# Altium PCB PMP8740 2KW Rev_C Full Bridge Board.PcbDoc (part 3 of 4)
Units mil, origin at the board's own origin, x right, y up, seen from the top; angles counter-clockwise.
Board outline 10366.14 x 5900 mil, 2 copper layers (Top Layer, Bottom Layer), stack 62 mil thick; 355 components, 213 nets, 1059 pads, 574 vias.
Unrouted connection lines stored in the file: 2.
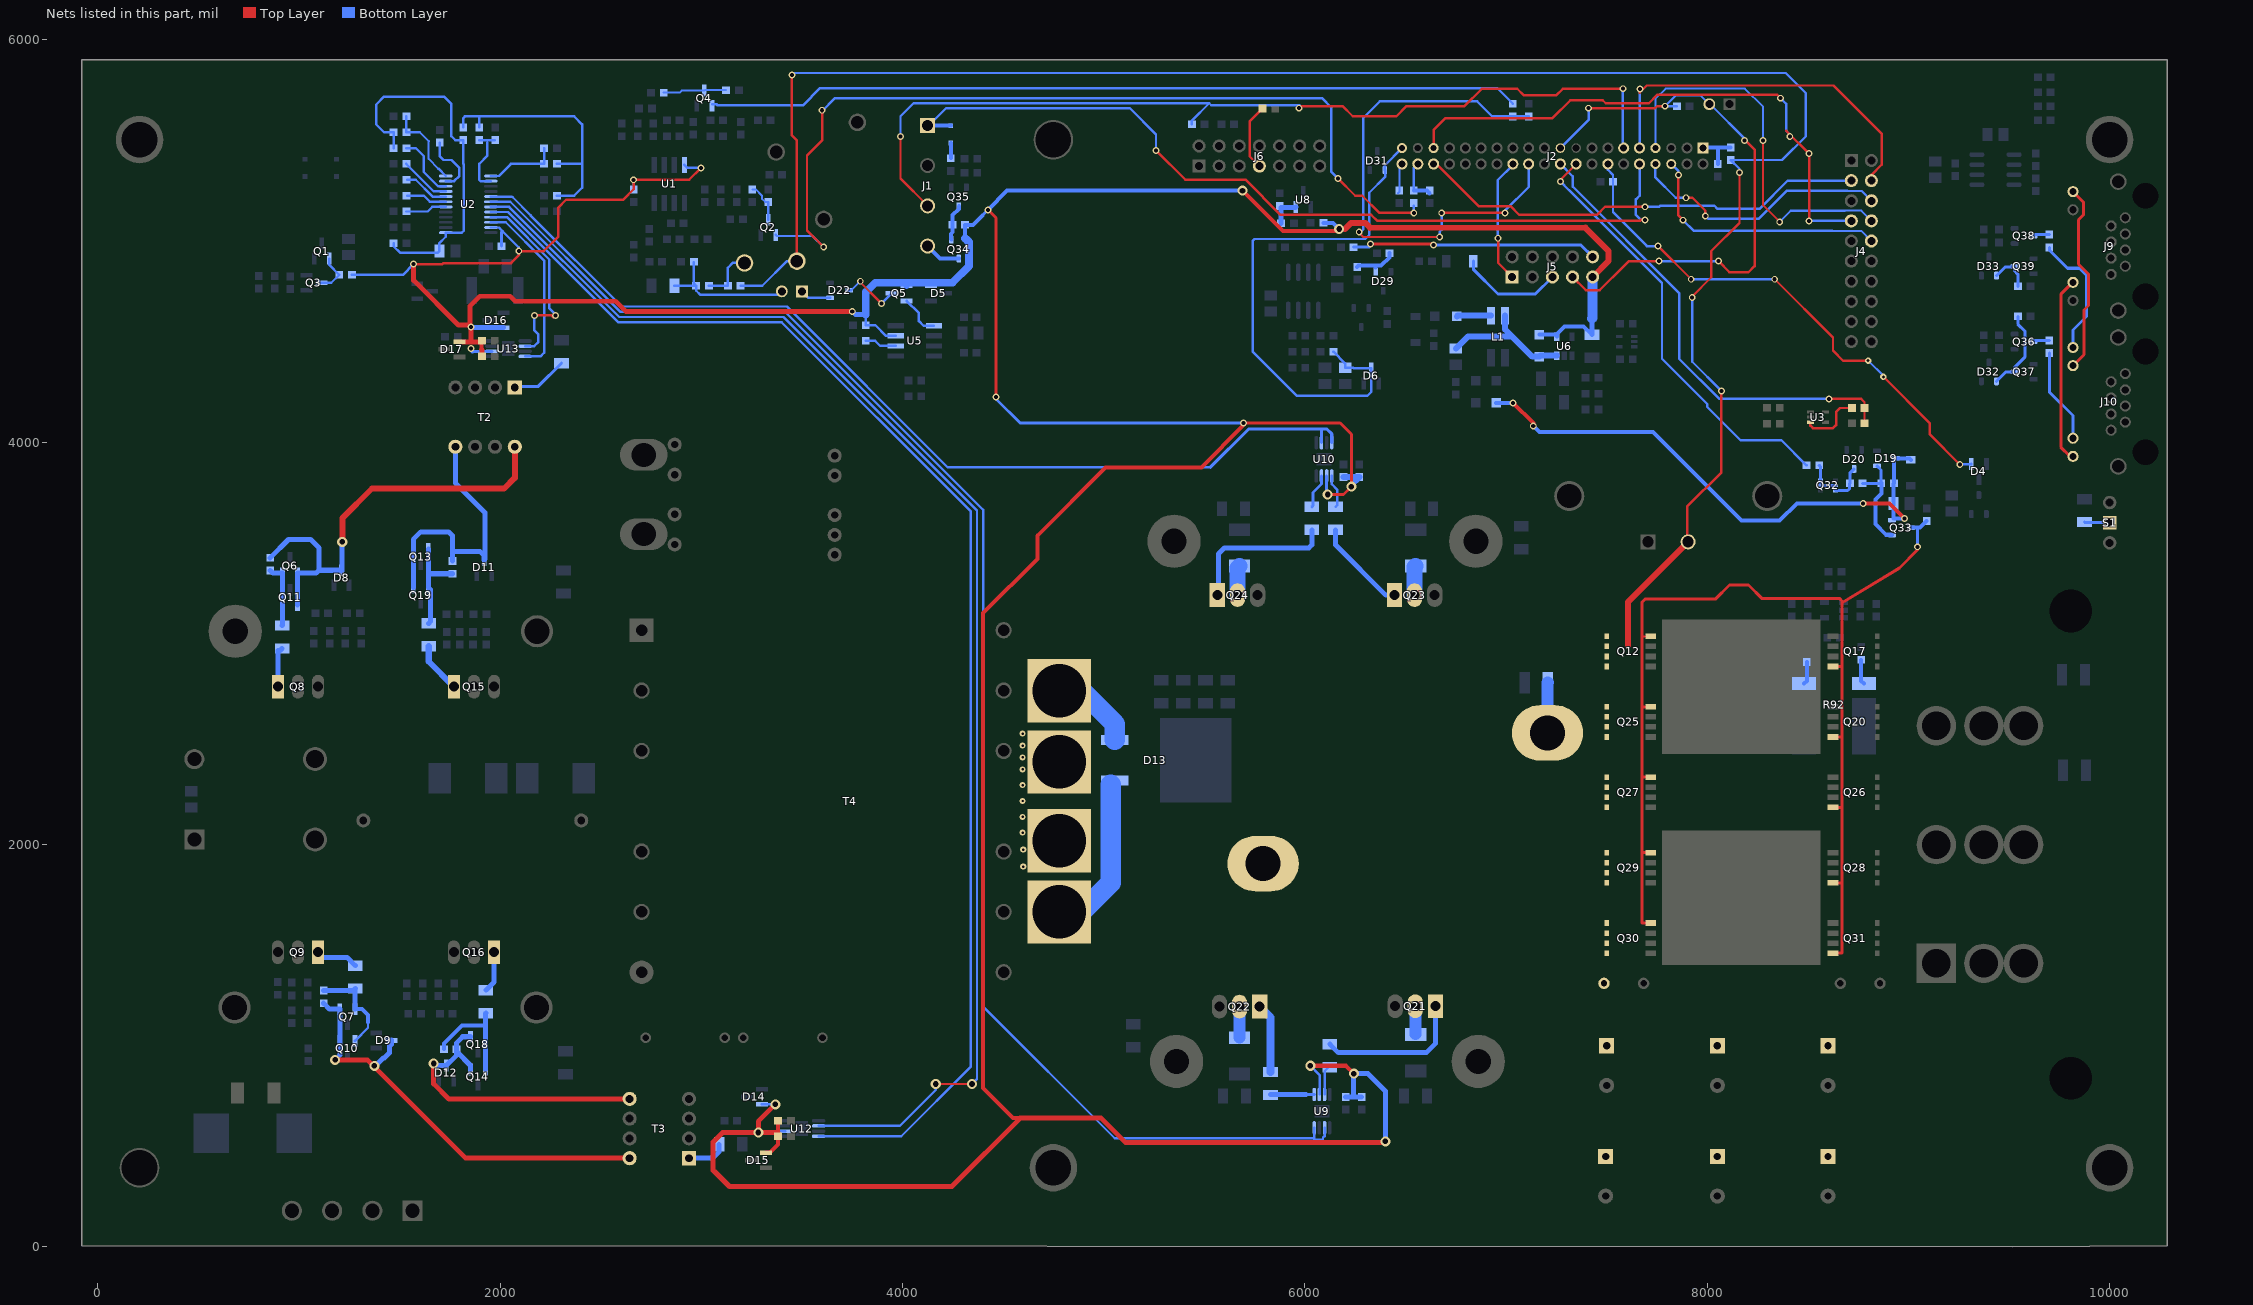
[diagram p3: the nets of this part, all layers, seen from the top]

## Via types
v1: diameter 34, hole 20, Top Layer to Bottom Layer, 367 vias
v2: diameter 50, hole 28, Top Layer to Bottom Layer, 60 vias
v3: diameter 34, hole 20, Top Layer to Bottom Layer, tented both sides, 45 vias
v4: diameter 30, hole 12, Top Layer to Bottom Layer, tented both sides, 34 vias
v5: diameter 50, hole 28, Top Layer to Bottom Layer, tented both sides, 33 vias
v6: diameter 19.68, hole 7.87, Top Layer to Bottom Layer, tented both sides, 20 vias
v7: diameter 34, hole 22, Top Layer to Bottom Layer, 11 vias
v8: diameter 34, hole 15, Top Layer to Bottom Layer, 3 vias
v9: diameter 30, hole 20, Top Layer to Bottom Layer, tented both sides, 1 vias

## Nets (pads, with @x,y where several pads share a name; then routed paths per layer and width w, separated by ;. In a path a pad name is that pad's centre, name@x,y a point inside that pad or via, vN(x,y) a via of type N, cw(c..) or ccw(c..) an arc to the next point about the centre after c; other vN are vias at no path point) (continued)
NetD8_3: D8.3 Q6.1 Q11.1 R72.1 T2.8 | length 2152.7
  Top Layer w30: v5(1215,3505) 1215.91,3505.91 1215.91,3622.88 1363.02,3770 2020,3770 2072.64,3822.64 T2.8@2072.64,3977.36
  Bottom Layer w25: R72.1@857.05,3425.55 947.6,3516.1 1057.83,3516.1 1099.17,3474.76 1099.17,3363.54 ; Q11.1@992.87,3191.3 Q6.1@992.87,3348.78 1084.41,3348.78 1099.17,3363.54 ; v5(1215,3505) 1215,3359.92 D8.3@1211.38,3363.54 1099.17,3363.54
NetD9_3: D9.3 Q7.1 Q10.1 R75.1 T3.8 | length 2210.7
  Top Layer w25: v5(1180,930) 1340,930 1829.02,440.98 T3.8@2643.62,440.98
  Bottom Layer w25: R75.1@1122.52,1211.3 1152.05,1181.77 Q7.1@1203.23,1181.77 Q10.1@1203.23,1024.29 1203.23,953.23 v5(1180,930) ; v5(1375,900) 1375,895 1420,940 1425,940 1449.29,964.29 1449.29,997.72 1459.13,1007.56 1459.13,1028.46 D9.3@1445.16,1028.46
NetD11_3: D11.3 Q13.1 Q19.1 R85.1 T2.5 | length 1391.2
  Bottom Layer w25: Q19.1@1568.23,3277.17 Q13.1@1568.23,3469.09 1568.23,3517.32 1605.63,3554.72 1743.43,3554.72 1763.11,3535.04 1763.11,3456.3 ; R85.1@1763.11,3409.06 1763.11,3456.3 ; T2.5@1777.36,3977.36 1777.36,3797.64 1925,3650 1925,3419.37 D11.3@1920.59,3414.96 1920.59,3436.61 1905.28,3451.93 ; 1900.91,3456.3 1763.11,3456.3
NetD12_3: D12.3 Q14.1 Q18.1 R88.1 T3.5 | length 1506.6
  Top Layer w25: v5(1669.33,911.97) 1669.33,810.67 1745,735 2642.36,735 T3.5@2643.62,736.26
  Bottom Layer w25: v5(1669.33,911.97) 1679.17,902.13 D12.3@1732.32,902.13 1783.5,953.31 R88.1@1783.5,971.02 ; Q14.1@1852.4,882.44 1852.4,902.13 R88.1@1783.5,971.02 ; Q18.1@1852.4,1044.84 1814.02,1044.84 1783.5,1014.33 R88.1@1783.5,982.83 R88.1@1783.5,971.02
NetD13_1: D13.1 Q21.2 Q22.2 R125.2 R126.2 T4.13 | length 1109.7
  Bottom Layer w59.06: R125.2@5675,1040.55 Q22.2@5675,1194.68 ; R126.2@6548.76,1057.2 Q21.2@6548.76,1196.57
  Bottom Layer w100: T4.13@4770,1660 4885,1660 5035,1810 D13.1@5035,2299.06
NetD13_3: D13.3 Q23.2 Q24.2 R127.2 R128.2 T4.16 | length 721.2
  Bottom Layer w80: Q24.2@5665,3240 5665,3374.45 R128.2@5675,3384.45 ; Q23.2@6545,3240 6545,3379.45 R127.2@6550,3384.45
  Bottom Layer w100: T4.16@4778.23,2765 4890,2765 5054.94,2600.06 D13.3@5054.94,2519
NetD19_1: D19.1 Q33.1 R80.1 R83.2 | length 509.1
  Bottom Layer w15: R83.2@8771.5,3795 8863.79,3795 8863.79,3861.57 D19.1@8842.76,3882.6
  Bottom Layer w20: R80.1@8864.89,3796.1 8864.89,3744.89 8835,3715 8835,3594.21 8889.21,3540 8915.35,3540 Q33.1@8917.76,3537.6
NetD20_3: D20.3 Q32.3 R83.1 | length 182
  Bottom Layer w15: Q32.3@8637.4,3759.41 8697.68,3759.41 8706,3767.73 8706,3792.5 R83.1@8708.5,3795 8708.5,3846.26 D20.3@8730,3867.76
NetD22_1: D22.1 J3.1 | length 153.2
  Bottom Layer w12: J3.1@3500,4750 3532.4,4717.6 D22.1@3639.8,4717.6
NetD22_3: D22.3 Q5.3 | length 311
  Top Layer w12: v1(3790,4800) 3785,4800 v1(3895,4690)
  Bottom Layer w12: D22.3@3734.29,4755 3745,4755 v1(3790,4800) ; v1@3895,4685 v1@3895,4689.49 ; v1(3895,4690) v1@3895,4689.49 ; Q5.3@3945.28,4739.77 v1@3895,4689.49
NetD24_1: D24.1 L1.4 | length 171.2
  Bottom Layer w30: D24.1@6755.12,4625 6759.45,4629.33 L1.4@6924.57,4629.33
NetD27_2: D27.2 L1.1 R91.2 U6.3 | length 689
  Bottom Layer w30: R91.2@6750,4465 6810,4525 7030,4525 ; L1.1@6995,4628.9 6995,4560 7030,4525 ; U6.3@7252.01,4430.31 7170.43,4430.31 D27.2@7165,4424.88 7130.12,4424.88 7030,4525
NetD28_1: D28.1 R105.2 | length 75.2
  Bottom Layer w20: R105.2@4240,5411.5 D28.1@4240,5486.69
NetD29_1: D29.1 R65.2 R67.1 | length 215
  Bottom Layer w20: R67.1@6260,4871.5 6265.75,4877.24 6342.64,4877.24 ; 6351.95,4867.93 6342.64,4877.24 ; R65.2@6421.5,4940 6420.99,4939.5 6420.99,4919 6379.23,4877.24 6342.64,4877.24
NetD32_1: D32.1 Q37.3 R118.2 | length 421.7
  Bottom Layer w15: D32.1@9437.4,4302.76 9437.76,4302.76 9485,4350 Q37.3@9527.76,4350 9527.76,4372.76 9580,4425 9580,4550 9543.5,4586.5 R118.2@9543.5,4625
NetD33_1: D33.1 Q39.3 R121.2 | length 216.4
  Bottom Layer w15: D33.1@9437.4,4827.76 9479.65,4870 9522.76,4870 Q39.3@9527.76,4875 9527.76,4850.67 9543.5,4834.92 R121.2@9543.5,4775
NetJ1_4: J1.4 Q34.3 | length 180.8
  Bottom Layer w20: J1.4@4125,4975 4187.24,4912.76 Q34.3@4280,4912.76
NetJ2_40: J2.40 R35.1 | length 153.8
  Bottom Layer w12: R35.1@6462.64,5237.4 6470,5244.76 6470,5370.75 J2.40@6482.32,5383.07
NetJ6_7: J6.7 R106.2 | length 333.1
  Top Layer w12: J6.7@5773.66,5372.44 5725,5421.1 5725,5594.25 R106.2@5789.41,5658.66
NetJ9_9: J9.9 J10.10 | length 949.1
  Top Layer w15: J10.10@9817.72,4380.31 9872.4,4435 9872.4,4657.4 9895,4680 9895,4835 9845,4885 9845,5105 9869.09,5129.09 9869.09,5194.09 J9.9@9817.72,5245.47
NetJ9_11: J9.11 J10.12 | length 924
  Top Layer w15: J10.12@9817.72,3929.53 9802.95,3929.53 9757.48,3975 9757.48,4735 9817.17,4794.69 J9.11@9817.72,4794.69
NetJ10_9: J10.9 R120.2 | length 637.7
  Bottom Layer w15: R120.2@9700,4968.5 9700,4955 9790.37,4864.63 9850.37,4864.63 9885,4830 9885,4625 9817.72,4557.72 J10.9@9817.72,4470.47
NetJ10_11: J10.11 R117.2 | length 472.6
  Bottom Layer w15: R117.2@9700,4443.5 9700,4250 9817.72,4132.28 J10.11@9817.72,4019.69
NetL3_1: L3.1 T4.14 T4.15
  other v4: 4600,1890 4600,1975 4597.28,2059.09 4597.28,2137.83 4597.28,2216.57 4597.28,2295.32 4597.28,2374.06 4597.28,2433.11 4597.28,2492.17 4597.28,2551.22
NetQ1_1: Q1.1 Q3.3 R30.2 | length 206
  Bottom Layer w12: Q3.3@1111.57,4792.52 1160.78,4792.52 R30.2@1200.15,4831.89 1150.94,4881.1 Q1.1@1150.94,4912.6
NetQ2_1: Q2.1 R28.2 | length 4435.6
  Top Layer w12: v1(3600,5650) 3600,5500 3525,5425 3525,5052.99 v3(3608.31,4969.69) ; v1(6165,5310) 6250,5225 6285,5225 6370,5140 v3(6541.38,5140)
  Bottom Layer w12: Q2.1@3370.12,5030.71 3375.83,5025 3552.99,5025 v3(3608.31,4969.69) ; v1@3600,5645 3665,5710 6085,5710 6130,5665 6130,5345 v1(6165,5310) ; v3(6541.38,5140) R28.2@6541.38,5174.41
NetQ2_3: Q2.3 R24.2 R25.2 | length 203
  Bottom Layer w10: R24.2@3253.98,5257.09 3270.29,5257.09 3301.06,5226.31 3301.06,5210 3316.97,5194.09 R25.2@3332.72,5194.09
  Bottom Layer w12: Q2.3@3332.72,5105.51 R25.2@3332.72,5194.09
NetQ4_1: Q4.1 R49.2 | length 4048.4
  Bottom Layer w12: Q4.1@3055.16,5680.31 3074.84,5680.31 3080.75,5674.41 3504.41,5674.41 3590,5760 6955.79,5760 R49.2@7033.5,5682.28
NetQ4_3: Q4.3 R45.2 R46.2 | length 315.7
  Bottom Layer w10: R45.2@2813.03,5737.4 2892.4,5737.4 2902.4,5747.4 Q4.3@3015,5747.4 3017.6,5750 R46.2@3123.5,5750
NetQ5_2: Q5.2 U5.5 | length 209.7
  Bottom Layer w12: Q5.2@4020.08,4702.37 4081.1,4641.34 4081.1,4601.97 4104.53,4578.55 U5.5@4155.42,4578.55
NetQ6_2: Q6.2 Q11.2 R72.2 R73.1 | length 327.4
  Bottom Layer w25: R72.2@857.05,3362.56 870.83,3348.78 Q6.2@918.07,3348.78 Q11.2@918.07,3191.3 918.07,3090.91 R73.1@916.1,3088.94
NetQ7_2: Q7.2 Q10.2 R74.1 R75.2 | length 494
  Bottom Layer w12: Q10.2@1278.03,1024.29 1342.99,1089.25 1342.99,1116.81
  Bottom Layer w20: Q7.2@1278.03,1181.77 1313.46,1181.77 1342.99,1152.24 1342.99,1116.81
  Bottom Layer w25: R75.2@1122.52,1274.29 1270.16,1274.29 R74.1@1278.03,1282.17 ; Q7.2@1278.03,1181.77 R74.1@1278.03,1282.17 ; R74.1@1280,1284.13 R74.1@1278.03,1282.17
NetQ8_1: Q8.1 R73.2 | length 220.1
  Bottom Layer w25: Q8.1@895,2770 895,2964.94 906.28,2964.94 R73.2@916.1,2974.76
NetQ9_1: Q9.1 R74.2 | length 192.7
  Bottom Layer w25: Q9.1@1104.41,1439.65 1238.66,1439.65 R74.2@1280,1398.31
NetQ12_4: Q12.4 Q17.4 Q20.4 Q25.4 Q26.4 Q27.4 Q28.4 Q29.4 Q30.4 Q31.4 Q33.3 R52.1 | length 5498.7
  Top Layer w10: 7675,3035 Q12.4@7719.3,3035
  Top Layer w15: Q30.4@7719.3,1610 7675,1610 7675,1960 ; Q29.4@7719.3,1960 7675,1960 ; Q27.4@7719.3,2335 7675,2335 ; Q25.4@7719.3,2685 7675,2685 ; Q31.4@8625.7,1460 8670,1460 8670,1810 ; Q28.4@8625.7,1810 8670,1810 ; Q26.4@8625.7,2185 8670,2185 ; Q20.4@8625.7,2535 8670,2535 ; Q17.4@8625.7,2885 8670,2885 ; v1@9045,3465 8955,3375 8670,3202.4 ; 7675,1960 7675,2335 ; 7675,2335 7675,2685 ; 7675,2685 7675,3035 7675,3205 7690,3220 8040,3220 8110,3290 8205,3290 8273.07,3221.93 8658.53,3221.93 8670,3210.45 8670,3202.4 ; 8670,1810 8670,2185 ; 8670,2185 8670,2535 ; 8670,2535 8670,2885 ; 8670,2885 8670,3202.4
  Bottom Layer w15: v1(9045,3480) 9045,3575
  Bottom Layer w20: Q33.3@9012.24,3575 9045,3575 9056.5,3575 R52.1@9090,3608.5
NetQ13_2: Q13.2 Q19.2 R85.2 R86.1 | length 499.8
  Bottom Layer w25: Q13.2@1643.03,3469.09 1643.03,3338.19 ; R86.1@1645,3100 1652.87,3107.87 1652.87,3267.32 Q19.2@1643.03,3277.17 1643.03,3338.19 ; R85.2@1763.11,3346.06 1650.91,3346.06 1643.03,3338.19
NetQ14_2: Q14.2 Q18.2 R87.1 R88.2 | length 552.2
  Bottom Layer w20: R88.2@1720.51,982.83 1720.51,1010.51 1810.94,1100.94 1927.2,1100.94
  Bottom Layer w25: Q14.2@1927.2,882.44 Q18.2@1927.2,1044.84 1927.2,1100.94 1927.2,1160 R87.1@1929.17,1161.97
NetQ15_1: Q15.1 R86.2 | length 252.6
  Bottom Layer w30: R86.2@1645,2985.83 1645,2910 Q15.1@1770,2785
NetQ16_1: Q16.1 R87.2 | length 205.8
  Bottom Layer w25: R87.2@1929.17,1276.14 1970.12,1317.09 Q16.1@1970.12,1465
NetQ21_1: Q21.1 R95.2 | length 739.6
  Bottom Layer w25: R95.2@6124.17,1007.68 6166.44,965.41 6603.4,965.41 6650,1012.01 Q21.1@6650,1189
NetQ22_1: Q22.1 R97.1 | length 347.1
  Bottom Layer w40: Q22.1@5775,1194.68 5828.9,1140.79 R97.1@5828.9,869.88
NetQ23_1: Q23.1 R99.1 | length 471
  Bottom Layer w25: R99.1@6152.4,3564.65 6152.4,3489.65 6402.05,3240 Q23.1@6445,3240
NetQ24_1: Q24.1 R96.2 | length 702.8
  Bottom Layer w25: 5570,3300 5570,3445 5600,3475 6019.65,3475 6034.29,3489.65 R96.2@6034.29,3564.65
NetQ32_2: Q32.2 Q32.5 Q32.6 R84.2 | length 177.3
  Bottom Layer w15: R84.2@8556.5,3885 8562.6,3878.9 Q32.6@8562.6,3810.59 Q32.5@8562.6,3785 Q32.2@8637.4,3785
NetQ34_1: Q34.1 Q35.3 R104.2 | length 183.2
  Bottom Layer w20: Q34.1@4242.6,5007.24 4240,5009.84 4240,5035.79 4248.5,5044.29 R104.2@4248.5,5080 4248.5,5128.5 4280,5160 Q35.3@4280,5172.76
NetQ36_3: Q36.3 R117.1 | length 80.4
  Bottom Layer w15: Q36.3@9622.24,4500 9628.74,4506.5 R117.1@9700,4506.5
NetQ38_3: Q38.3 R120.1 | length 80.4
  Bottom Layer w15: Q38.3@9622.24,5025 9628.74,5031.5 R120.1@9700,5031.5
NetR1_1: R1.1 R5.2 R6.2 R8.2 | length 1295.7
  Bottom Layer w12: R1.1@1816.97,5564.17 1816.97,5611.42 1824.84,5619.29 1895.71,5619.29 ; R5.2@1895.71,5564.17 1895.71,5619.29 ; R8.2@2281.54,5225.59 2368.15,5225.59 2407.52,5264.96 2407.52,5383.07 ; R6.2@2281.54,5383.07 2407.52,5383.07 ; 1895.71,5619.29 2368.15,5619.29 2407.52,5579.92 2407.52,5383.07
NetR5_1: R5.1 R16.2 U2.14 | length 341.2
  Bottom Layer w12: R5.1@1895.71,5501.18 R16.2@1974.45,5501.18 ; 1935.08,5489.37 1935.08,5422.44 1895.71,5383.07 1895.71,5304.33 1902.4,5297.64 U2.14@1954.09,5297.64
NetR6_1: R6.1 R17.2 U2.13 | length 368
  Bottom Layer w12: U2.13@1954.09,5323.23 1993.35,5323.23 2053.19,5383.07 R6.1@2218.54,5383.07 R17.2@2218.54,5461.81
NetR7_1: R7.1 R18.2 U2.12 | length 416.5
  Bottom Layer w10: 1645,5495.98 1645,5407.92 1692.92,5360
  Bottom Layer w12: R18.2@1533.5,5619.29 R7.1@1533.5,5540.55 1600.43,5540.55 1645,5495.98 ; 1692.92,5360 U2.12@1729.68,5323.23
NetR9_2: R9.2 U2.6 | length 205.6
  Bottom Layer w12: R9.2@1533.5,5146.85 1639.8,5146.85 1662.64,5169.69 U2.6@1729.68,5169.69
NetR10_2: R10.2 U2.7 | length 203.5
  Bottom Layer w12: R10.2@1538.74,5225.59 1620.12,5225.59 1650.43,5195.28 U2.7@1729.68,5195.28
NetR11_2: R11.2 U2.8 | length 225.5
  Bottom Layer w12: R11.2@1538.74,5304.33 1580.75,5304.33 1664.21,5220.87 U2.8@1729.68,5220.87
NetR12_2: R12.2 R14.1 TP2.1 | length 276.5
  Bottom Layer w12: R14.1@3037.44,4777.76 R12.2@3131.93,4777.76 3131.93,4867.32 3155.55,4890.94 TP2.1@3214.61,4890.94
NetR15_1: R15.1 U2.10 | length 320.9
  Bottom Layer w12: R15.1@1533.5,5461.81 1580.75,5461.81 1620.12,5422.44 1620.12,5343.7 1691.77,5272.05 U2.10@1729.68,5272.05
NetR20_2: R20.2 U2.11 | length 307.7
  Bottom Layer w12: R20.2@1698.86,5489.37 1698.86,5422.44 1718.54,5402.76 1757.91,5402.76 1797.28,5363.39 1797.28,5324.02 1770.91,5297.64 U2.11@1729.68,5297.64
NetR22_2: R22.2 U2.9 | length 252.8
  Bottom Layer w12: R22.2@1533.5,5383.07 1670.11,5246.46 U2.9@1729.68,5246.46
NetR41_1: R41.1 U3.3 | length 307.5
  Top Layer w12: U3.3@8512.6,4099.41 8512.6,4082.4 8525,4070 8625,4070 8640,4085 8640,4150 8660,4170 R41.1@8718.5,4170
NetR56_1: R56.1 U5.2 | length 159.4
  Bottom Layer w12: R56.1@3817.32,4503.55 3864.57,4503.55 3889.57,4478.55 U5.2@3966.42,4478.55
NetR63_1: R63.1 R66.2 U8.2 | length 152.4
  Bottom Layer w25: R63.1@5881.93,5087.8 5881.93,5166.54 5952.8,5166.54 U8.2@5954.76,5168.5
NetR78_2: R78.2 T2.1 | length 280.1
  Bottom Layer w15: T2.1@2072.64,4277.64 2189.72,4277.64 R78.2@2305,4392.91
NetR79_2: R79.2 T3.1 | length 200.1
  Bottom Layer w25: T3.1@2938.9,440.98 3057.01,440.98 3088.5,472.48 R79.2@3088.5,509.88
NetR92_1: R92.1 R93.2 | length 123.5
  Bottom Layer w20: R93.2@8765,2918.5 8765,2814.1 R92.1@8778.5,2800.6
NetR92_3: R92.3 R94.2 | length 113.5
  Bottom Layer w20: R92.3@8481.5,2800.6 8495,2814.1 R94.2@8495,2908.5
NetR95_1: R95.1 U9.7 | length 153.9
  Bottom Layer w12: U9.7@6098.84,757.68 6098.84,874.02 R95.1@6125.41,900.6
NetR96_1: R96.1 U10.7 | length 173.4
  Bottom Layer w15: R96.1@6034.29,3678.82 6040,3684.53 6040,3750 6082.2,3792.2 U10.7@6082.2,3832.32
NetR97_2: R97.2 U9.5 | length 216.6
  Bottom Layer w15: 6005.34,758.39 6006.05,757.68 U9.5@6046.42,757.68
  Bottom Layer w25: R97.2@5830.14,758.39 6005.34,758.39
NetR99_2: R99.2 U10.5 | length 167.7
  Bottom Layer w12: U10.5@6133.39,3832.32 6133.39,3791.61 6160,3765 6160,3686.42 R99.2@6152.4,3678.82
NetR116_2: R116.2 S1.1 | length 126.2
  Bottom Layer w15: R116.2@9875,3602.91 9877.91,3600 S1.1@10000,3600
OUT-A: U2.22 U13.4 | length 902.9
  Bottom Layer w12: U2.22@1954.09,5092.92 2027.98,5092.92 2218.35,4902.56 2218.35,4444.96 2199.65,4426.26 U13.4@2123.86,4426.26
OUT-B: U2.21 U13.2 | length 996.3
  Top Layer w12: v1(2170,4630) 2255,4630 2265,4620 v1(2275,4630)
  Bottom Layer w12: U2.21@1954.09,5118.51 2033.5,5118.51 2245,4907.01 2245,4665 2275,4635 v1(2275,4630) ; U13.2@2123.86,4477.44 2169.61,4477.44 2190,4497.83 2190,4535 2170,4555 v1(2170,4630)
OUT-C: U2.20 U12.4 | length 6662.2
  Bottom Layer w12: U2.20@1954.09,5144.1 2039.03,5144.1 2587.46,4595.67 3399.33,4595.67 4340,3655 4340,896.3 3993.94,550.24 U12.4@3582.6,550.24
OUT-D: U2.19 U12.2 | length 6767.8
  Top Layer w12: v2(4165,810) v2(4345,810)
  Bottom Layer w12: U2.19@1954.09,5169.69 2044.55,5169.69 2591.79,4622.45 3407.55,4622.45 4370,3660 4370,835 v2(4345,810) ; U12.2@3582.6,601.42 3986.06,601.42 4165,780.35 v2(4165,810)
OUT-E: U2.18 U9.2 U9.4 | length 7633.9
  Bottom Layer w12: U2.18@1954.09,5195.28 2050.07,5195.28 2597.5,4647.85 3417.15,4647.85 4400.43,3664.57 4400.43,1194.57 5055,540 6046.26,540 ; U9.4@6046.42,592.32 6046.42,534.81 6045,533.39 6090,533.39 6090,543.39 6097.6,550.99 U9.2@6097.6,592.32
OUT-F: U2.17 U10.2 U10.4 | length 4936.9
  Bottom Layer w12: U2.17@1954.09,5220.87 2057.91,5220.87 2061.5,5217.28 2062.3,5217.28 2151.61,5127.97 2151.61,5127.17 2604.37,4674.41 3425.59,4674.41 4225,3875 5530,3875
  Bottom Layer w15: 5530,3875 5720,4065 6082.2,4065 ; U10.2@6082.2,3997.68 6082.2,4065 ; U10.4@6133.39,3997.68 6133.39,4041.61 6110,4065 6082.2,4065
PARALLEL_BIAS: C5.1 J3.2 R13.2 R14.2 | length 689.6
  Bottom Layer w12: R13.2@2866.18,4777.76 R14.2@2974.45,4777.76 ; C5.1@2962.64,4895.87 2962.64,4789.57 R14.2@2974.45,4777.76 ; J3.2@3400,4733.46 2994.13,4733.46 2974.45,4753.15 R14.2@2974.45,4777.76
"PFC_ON P2.5": J2.26 J5.1 | length 625.7
  Top Layer w12: v3(6960,5013.76) 6960,5010 6960,4891.61 J5.1@7030.35,4821.26
  Bottom Layer w12: v3@6958.7,5010 6958.7,5302.54 7033.5,5377.34 J2.26@7033.5,5383.07
"PG_PFC P2.1": J2.19 J5.7 J11.2 R115.1 | length 2886.5
  Top Layer w12: J5.7@7330.35,4821.26 7396.61,4755 7465,4755 7585.18,4875.18 ; v1(7410,5660) 7740,5660 7750,5670 v1(7790,5670) ; 7585.35,4875 7610.35,4900 v1(7760,4900) ; v1(8055,4900) 8110,4845 8205,4845 8235,4875 8235,5455 8200,5490
  Bottom Layer w12: J2.19@7269.72,5461.81 7410,5602.09 v1(7410,5660) ; v1(7760,4900) v1(8055,4900) ; R115.1@7848.5,5670 v1(7790,5670) 7844.83,5724.83 7965.17,5724.83 J11.2@8010,5680 8015,5680 8195,5500 v1(8185,5500)
"PRE-CHARGE P2.2": J2.18 R84.1 | length 2147.9
  Top Layer w12: v1@7270,5304.61 J2.18@7348.46,5383.07
  Bottom Layer w12: v1(7270,5295) 7311.62,5253.38 7313.26,5253.38 7775,4791.64 7775,4415 8000,4190 8000,4175 8165,4010 8368.5,4010 R84.1@8493.5,3885
"PWM_IREF P2.3": J2.24 R49.1 R51.1 | length 2619.9
  Top Layer w12: v3@6270,5050 6270,5040 6290,5020 v3(6670,5020) ; v3(6680,5140) v3(6995,5140)
  Bottom Layer w12: v3(6270,5045) 6270,5040 v3@6270,5050 ; v3@6280,5047.5 6290,5057.5 6290,5612.01 6372.09,5694.09 6856.34,5694.09 6931.14,5619.29 R49.1@7033.5,5619.29 R51.1@7112.24,5619.29 ; v3(6670,5020) 6670,5045.79 6680,5055.79 v3(6680,5140) ; v3(6995,5140) 6995,5151.28 7112.24,5268.52 J2.24@7112.24,5383.07
"PWM_VREF P2.4": J2.38 R28.1 R31.1 | length 225.2
  Bottom Layer w12: R28.1@6541.38,5250 6541.38,5363.39 J2.38@6561.06,5383.07
  Bottom Layer w20: R28.1@6541.38,5250 6607.52,5250 R31.1@6620.12,5237.4
"R/W P1.2": J2.35 J4.7 | length 2830.7
  Top Layer w12: J2.35@6639.8,5461.81 6639.8,5551.98 6698.86,5611.04 7230.35,5611.04 7319.31,5700 7480,5700 7495,5685 7709.45,5685 7750.87,5726.42 8347.63,5726.42 v1(8364.21,5709.84) ; 8391.77,5548.43 v1(8505.94,5434.25) v1(8505.94,5100) ; v1(8410,5520) v1@8410,5530.2
  Bottom Layer w12: v1(8364.21,5709.84) 8391.77,5682.28 8391.77,5548.43 8410,5530.2 v1(8410,5520) ; v1(8505.94,5100) J4.7@8715.79,5100
"REVERSE POLARITY P3.3": D4.1 J2.14 R55.2 | length 2624.7
  Top Layer w12: v1(7755,4975) v1(7920,4810) ; v1(8335,4810) 8625,4520 8625,4455 8675,4405 v8(8800,4405) ; v8(8875,4325) 9105,4095 9105,4040 v1(9255,3890)
  Bottom Layer w12: J2.14@7505.94,5383.07 7505.94,5354.06 7531.5,5328.5 R55.2@7531.5,5295 7531.5,5143.5 7700,4975 v1(7755,4975) ; v1(7920,4810) v1(8335,4810) ; v8(8800,4405) 8875,4330 v8(8875,4325) ; v1(9255,3890) 9310.2,3890 D4.1@9312.6,3892.4
"RS P1.1": J2.36 J4.3 | length 2263.7
  Top Layer w12: J2.36@6639.8,5383.07 6654.11,5383.07 6863.6,5173.58 7021.57,5173.58 7065.16,5130 7451.91,5130 7491.91,5170 7635,5170 v1(7690,5170)
  Bottom Layer w12: v1(7690,5170) 7760.59,5170 7765.59,5175 8035,5175 8050,5160 8260,5160 8400,5300 J4.3@8715.79,5300
"S1 (ESC) P4.5": J2.6 J4.10 | length 1282.7
  Top Layer w12: v1(7856.34,5327.95) 7856.34,5127.17 v1(7879.96,5103.54)
  Bottom Layer w10: 8620.8,5049.99 8765.8,5049.99 J4.10@8815.79,5000
  Bottom Layer w12: J2.6@7820.91,5383.07 7856.34,5347.64 v1(7856.34,5327.95) ; v1(7879.96,5103.54) 7933.51,5049.99 8620.8,5049.99
"S2 (-) P4.4": J2.7 J4.8 | length 2003.8
  Top Layer w10: v3@8277.6,5487.6 v3(8277.6,5500) 8277.6,5177.4 v1(8360,5095)
  Bottom Layer w10: J2.7@7742.17,5461.81 7742.17,5706.53 7793.35,5757.71 8186.43,5757.71 8277.6,5666.54 v3@8277.6,5489.37 ; v3@8277.6,5487.6 v3(8277.6,5500) ; v1(8360,5095) 8415.79,5150.79 ; 8659.49,5150.79 8695.02,5150.79 8695.29,5150.52 8765.27,5150.52 J4.8@8815.79,5100
  Bottom Layer w12: 8415.79,5150.79 8659.49,5150.79 8683.11,5150.79
"S3 (+) P4.3": J2.8 J4.6 | length 1319.4
  Top Layer w12: v1(7895,5215) 7925.98,5215 7990,5150.98 v1(7990,5125)
  Bottom Layer w10: 8695.02,5249.21 8695.29,5249.48 8736.28,5249.48 8736.55,5249.21 8766.57,5249.21 J4.6@8815.79,5200
  Bottom Layer w12: J2.8@7742.17,5383.07 7742.17,5316.14 7843.31,5215 v1(7895,5215) ; v1(7990,5125) 8005,5110 8255,5110 8394.21,5249.21 8695.02,5249.21
"S4 (ENTER) P4.2": J2.9 J4.4 | length 1883.8
  Top Layer w12: v1(7665,5755) 7665,5738.98 7663.43,5737.4 7698.86,5772.83 8627.99,5772.83 8866.27,5534.56 8866.27,5379.09 8815.79,5328.61 J4.4@8815.79,5300
  Bottom Layer w12: J2.9@7663.43,5461.81 7663.43,5737.4 7665,5738.98 v1(7665,5755)
"SPEED_READING P4.0": J1.3 J2.11 R26.1 | length 4692.4
  Top Layer w12: v1(3990,5520) 3990,5310 J1.3@4125,5175 ; v3(5970,5660) 5975,5660 5985.53,5670.53 6187.5,5670.53 6238.03,5620 6455,5620 6505.53,5670.53 6793.41,5670.53 6879.96,5757.09 7055.16,5757.09 7087.24,5725 7250,5725 7282.09,5757.09 v1(7580.75,5757.09)
  Bottom Layer w12: v1(3990,5520) 3990,5620 3990.08,5620 4055.08,5685 5524.41,5685 ; R26.1@5438.5,5580 5438.5,5599.09 5524.41,5685 ; v3@5975,5660 5975,5673 5973,5675 5534.41,5675 5524.41,5685 ; v1(7580.75,5757.09) 7580.75,5465.75 J2.11@7584.68,5461.81
  Bottom Layer w20: J1.3@4139.8,5169.88 J1.3@4143.15,5166.54
"SPEED_SET P4.1": D28.2 J1.1 J2.10 | length 4308.6
  Top Layer w12: v1(5260,5450) 5405,5305 5704.09,5305 5879.09,5130 6330,5130 6360,5100 7665,5100 7670,5105 v1(7690,5105)
  Bottom Layer w12: J1.1@4130,5573.31 4216.69,5660 5130,5660 5260,5530 v1(5260,5450) ; J2.10@7663.43,5383.07 7663.43,5225 7645,5206.57 7645,5130 7670,5105 v1(7690,5105)
  Bottom Layer w20: J1.1@4125,5575 4126.69,5573.31 D28.2@4240,5573.31
"TEMP-1 P2.0": J2.20 R41.2 R103.2 | length 2327.2
  Top Layer w12: v1(8605,4215) 8765,4215 8781.5,4198.5 R41.2@8781.5,4170 R103.2@8781.5,4095
  Bottom Layer w12: J2.20@7269.72,5383.07 7331.4,5321.4 7331.4,5270.22 7860,4741.61 7860,4415 8060,4215 v1(8605,4215)
V-FLOAT: C57.2 D18.1 D19.3 D23.1 Q33.2 R80.2 | length 2785.9
  Top Layer w20: v1(7034.88,4194.88) 7035,4195 7135,4095 v1(7135,4080) ; v1(8775,3695) 8905,3695 v1(8980,3620)
  Bottom Layer w20: D23.1@6950,4194.88 v1(7034.88,4194.88) ; v1(7135,4080) 7165,4050 7730,4050 8170,3610 8360,3610 8445,3695 v1(8775,3695) ; v1(8980,3620) 8925.35,3620 8925,3619.65 C57.2@8925,3695 8925,3793.22 R80.2@8927.88,3796.1 8927.88,3910.63 D19.3@8937.24,3920 9004.43,3920 D18.1@9011.99,3912.44
VAC: C81.1 J5.5 | length 520.5
  Bottom Layer w15: C81.1@6836.93,4900 6836.93,4859.17 6960,4736.1 7145.2,4736.1 J5.5@7230.35,4821.26
"VAC_IN P4.6": C89.1 D6.3 D31.1 J2.39 R113.1 | length 2685.7
  Bottom Layer w12: R113.1@6141.5,4450 6200,4391.5 C89.1@6200,4370 6240,4370 6242.6,4367.4 D6.3@6330,4367.4 6330,4250 6310,4230 5960,4230 5740,4450 5740,5000 5750,5010 6300,5010 6320,5030 6320,5240 6400,5320 6400,5350.16 D31.1@6397.4,5352.76 6397.4,5376.89 J2.39@6482.32,5461.81
VAC_RTN: J5.10 R114.1 | length 1236.4
  Top Layer w15: v1@6325,4985 v1(6326.37,4985) 6635,4985 v1(6640,4980)
  Bottom Layer w15: R114.1@6241.5,4970 6320,4970 6320,4978.63 v1(6326.37,4985) v1@6332.37,4991 ; v1(6640,4980) 7371.61,4980 J5.10@7430.35,4921.26
VCC_FB: C3.2 C10.1 C22.1 C25.1 C60.1 C61.1 C62.1 C63.1 C68.1 C69.1 C70.1 C71.1 D5.2 D14.2 D15.2 D16.2 D17.2 D27.1 J5.9 Q5.1 Q34.2 R30.1 R60.2 R104.1 U1.8 U2.23 U5.3 U6.4 U9.6 U10.6 U12.6 U13.6 | length 24386.9
  Top Layer w12: v3(1570,4885) 1712.6,4885 1717.6,4890 2054.13,4890 2094.45,4930.31 2092.56,4930.31 ; v3(2092.56,4950) 2216.61,4950 2289.41,5022.8 2289.41,5166.54 2328.78,5205.91 2612.24,5205.91 2663.43,5257.09 v3(2663.43,5304.33) 2939.02,5304.33 v3(2998.07,5363.39)
  Top Layer w15: v1(4425,5155) 4465,5115 v1(4465,4225) ; v1(5695,4095) 6175,4095 6231.14,4038.86 v5(6231.14,3779.21) 6191.77,3739.84 v5(6113.03,3739.84)
  Top Layer w20: 1907.77,4460.71 C71.1@1907.77,4502.5 ; D15.2@3320.79,468.54 3340.47,468.54 3381.81,509.88 C69.1@3381.81,549.25 ; 3381.81,568.94 C68.1@3381.81,627.99 ; 4585,640 4550,640 4400,790 4400,3150 4670,3420 4670,3535 5010,3875 5485,3875 5695,4085 v1(5695,4095) ; v2(5690,5250) 5890,5050 6170,5050 v2(6170,5060) ; v5(6026.99,900.6) 6204.15,900.6 v5(6243.52,861.23)
  Top Layer w23.62: v3(1855,4572.09) 1844.33,4582.76 1850,4588.43 1850,4676.38 1898.62,4725 2050,4725 2075,4700 2575,4700 2625,4650 v1(3750,4650)
  Top Layer w25: v3(1570,4885) 1570,4805 1792.24,4582.76 v3@1844.33,4582.76 ; D17.2@1797.4,4498.82 1855,4498.82 ; v3(1855,4572.09) 1855,4498.82 ; 1907.77,4460.71 1910.28,4458.2 C70.1@1910.28,4426.26 ; C71.1@1907.77,4502.5 1904.09,4498.82 1855,4498.82 ; 3058.98,379.96 3058.98,521.69 3106.22,568.94 v5(3283.39,568.94) ; 3065,375 3140,300 4245,300 4585,640 4987.5,640 5107.5,520 6395,520 v2(6400,525) ; v5(3368.03,708.7) 3283.39,624.06 v5(3283.39,568.94) ; 3381.81,568.94 v5(3283.39,568.94)
  Top Layer w28: 6324,5066 7394,5066
  Top Layer w30: 6200,5060 6230,5090 6300,5090 6324,5066 ; 7394,5066 7510,4950 7510,4900.91 J5.9@7430.35,4821.26
  Bottom Layer w12: R30.1@1263.15,4831.89 1516.89,4831.89 v3(1570,4885) ; U2.23@1954.09,5067.33 1993.35,5067.33 2010.68,5050 2092.56,4968.12 v3(2092.56,4950) ; C3.2@2663.43,5257.09 v3(2663.43,5304.33) ; U1.8@2915.59,5378.65 2930.85,5363.39 v3(2998.07,5363.39) ; v5(3283.39,568.94) 3290.28,575.83 U12.6@3417.24,575.83 ; D14.2@3301.1,708.7 v5(3368.03,708.7) ; 3817.32,4635.04 C22.1@3817.32,4582.29 3864.57,4582.29 3918.31,4528.55 U5.3@3966.42,4528.55 ; v5(6026.99,900.6) 6073.25,854.34 U9.6@6073.25,757.68
  Bottom Layer w15: v1@1863.15,4451.85 U13.6@1958.5,4451.85 ; C10.1@2006.5,4975 2006.5,5045.81 2010.68,5050 ; 4397.5,5127.5 v1(4425,5155) ; v1(4465,4225) 4465,4215 4585,4095 v1(5695,4095) ; U10.6@6107.8,3832.32 6107.8,3745.08 v5(6113.03,3739.84)
  Bottom Layer w20: v1(1855,4465) 1855,4460 v1@1863.15,4451.85 ; Q34.2@4311.5,5013.15 R104.1@4311.5,5080 4350,5080 4397.5,5127.5 ; v1(4425,5155) 4520,5250 v2(5690,5250) ; R60.2@6091.5,5090 6140,5090 v2(6170,5060) ; D27.1@7165,4535.12 7241.69,4535.12 U6.4@7252.01,4524.8 7252.01,4538.58 7289.41,4575.98 7385.87,4575.98 C25.1@7427.2,4534.65
  Bottom Layer w23.62: v1(3750,4650) 3764.96,4635.04 3817.32,4635.04
  Bottom Layer w25: v3@1858.07,4569.02 D16.2@2017.4,4569.02 ; C60.1@6202.91,745.87 6242.28,745.87 ; v5@6242.28,859.99 6242.28,745.87 ; v5(6243.52,861.23) 6313.77,861.23 6400,775 v2(6400,525) ; C61.1@6281.65,745.87 6242.28,745.87 ; C25.1@7427.2,4534.65 7427.2,4615.35
  Bottom Layer w30: Q5.1@4020.08,4777.17 4020.08,4792.52 ; C62.1@6191.77,3826.46 C63.1@6270.51,3826.46 v5@6231.14,3787.09
  Bottom Layer w39.37: 3817.32,4635.04 3817.32,4745.63 3864.21,4792.52 4020.08,4792.52 4247.52,4792.52 4330,4875 4330,4994.65 Q34.2@4317.4,5007.24 Q34.2@4311.5,5013.15
  Bottom Layer w50: 7427.2,4615.35 7430.35,4618.5 J5.9@7430.35,4821.26
VOUT: C19.1 C29.1 C48.1 C53.1 C54.1 C55.1 C56.1 L3.2 Q12.5 Q12.6 Q12.7 Q12.8 Q25.5 Q25.6 Q25.7 Q25.8 Q27.5 Q27.6 Q27.7 Q27.8 Q29.5 Q29.6 Q29.7 Q29.8 Q30.5 Q30.6 Q30.7 Q30.8 R12.1 R42.2 R98.2 RT1.1 TP3.1 | length 10035
  Top Layer w12: v1(3450,5825) 3450,5525 3475,5500 TP3.1@3475,4925 ; TP3.1@3475,4900 TP3.1@3500,4925 ; R98.2@7905,3505 7900,3510 7900,3680 8070,3850 v1(8070,4255) ; v1(7925,4720) 7925,4725 8020,4820 8020,4950 8160,5090 v1(8160,5340)
  Top Layer w30: 7605,2990 7605,3205 R98.2@7905,3505
  Bottom Layer w12: R12.1@3194.92,4777.76 3302.76,4777.76 3425,4900 TP3.1@3475,4900 ; v1(3450,5825) 3460,5835 8390,5835 8490.2,5734.8 8490.2,5520.87 8372.09,5402.76 R42.2@8116.18,5402.76 8160,5358.94 v1(8160,5340) ; v1(7925,4720) 7925,4400 v1(8070,4255)
  Bottom Layer w60: L3.2@7205.71,2554.8 7205.71,2803.62 C48.1@7207.09,2805
"VOUT FB P3.6": J2.1 R42.1 R47.1 | length 222.1
  Bottom Layer w20: J2.1@7978.39,5461.81 7982.32,5465.75 8053.19,5465.75 ; R47.1@8053.19,5383.07 8053.19,5465.75 ; R42.1@8116.18,5465.75 8053.19,5465.75
VREF: C4.1 R1.2 R2.2 R7.2 R15.2 U2.1 | length 1822.5
  Bottom Layer w12: R2.2@1470.51,4989.37 1470.51,4973.62 1502.01,4942.13 1690.35,4942.13 C4.1@1698.23,4950 1698.23,4990 1729.68,5021.45 U2.1@1729.68,5041.74 1810.28,5041.74 1819.28,5050.74 1819.28,5380.76 1816.97,5383.07 R1.2@1816.97,5501.18 1777.6,5501.18 1757.91,5520.87 1757.91,5681.49 1721.68,5717.72 1423.27,5717.72 1383.9,5678.35 1383.9,5579.92 1423.27,5540.55 R7.2@1470.51,5540.55 R15.2@1470.51,5461.81
pads on no net: D2.2 D4.2 D6.2 D19.2 D20.2 D21.2 D22.2 D29.2 D30.2 D31.2 D32.2 D33.2 HS1.2 HS2.1 HS3.2 HS4.2 J2.5 J4.16 J4.18 J4.20 J6.2 J6.3 J6.5 J6.6 J6.10 J6.11 J6.12 J6.13 J6.14 J8.MH1 J8.MH2 J9.3 J9.6 J9.7 J9.MH1 J9.MH2 J9.MH3 J9.MH4 J10.3 J10.6 J10.7 J10.MH1 J10.MH2 J10.MH3 J10.MH4 S1.2 T2.2 T2.3 T3.2 T3.3 T4.2 T4.3 T4.4 T4.5 T4.7 T4.8 T4.9 T4.10 T4.11 T4.12 T7.8 T7.9 T7.10 T7.11 T7.12 TP4.1 TP13.1 U2.16 U6.1 U7.1 U7.3 U9.1 U9.8 U10.1 U10.8 U12.1 U12.8 U13.1 U13.8 U14.8

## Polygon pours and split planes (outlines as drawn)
GND-S on Bottom Layer "Bottom Layer-No Net 21" (solid, pour order 40): 3680,1191.38 4330,1191.38 4330,500 4190,360 3460,360 3455,365 3455,970
NetD13_1 on Bottom Layer "Bottom Layer-No Net 8" (solid, pour order 85): 4565,1810 4970,1810 4970,1390 4925,1345 4585,1345 4565,1365
NetD13_3 on Bottom Layer "Bottom Layer-No Net 7" (solid, pour order 82): 4575,3010 4895,3010 4960,2945 4960,2640 4930,2610 4582.27,2610 4575.13,2617.14
GND-S on Bottom Layer "Bottom Layer-gndx" (solid, pour order 116): 1038.13,5831.53 500,5830.13 500,4400 3006.64,4410.27 3773.35,4414.15 4280,3900 5475,3900 5683.8,4099.25 8225,4100 8350,3975 10250,3975 10250,5825 4660.18,5831.53 4640.49,5829.39 4246.79,5829.39 4109,5831.53
GND-S on Bottom Layer "Bottom Layer-No Net 20" (solid, pour order 106): 6045,3945 6150,3945 6147.05,4190 6367.05,4190 6365,3875 6046,3873.95
+390V on Bottom Layer "Bottom Layer-No Net 6" (solid, pour order 107): 805,770 1510,770 1735,545 1735,85 1695,45 1675,25 1670,30 799.65,30 805,35.35 805,770
GND-P on Bottom Layer "Bottom Layer-No Net 4" (solid, pour order 105): 2320,2500 2405,2585 3060,2585 3175,2470 3175,1275 2720,820 2115,820 2170,825 2170,1390 2040,1525 1980,1585 1820,1585 1805,1570 1805,1425 1785,1405 1640,1405 1585,1460 1585,1570.41 1625,1610.41 1625.41,1610.41 1885,1870 1885,2070 1925,2110 2240,2110 2320,2190
NetD7_2 on Bottom Layer "Bottom Layer-No Net 3" (solid, pour order 96): 1915,2515 2490,3090 2490,3657.8 2544.64,3712.44 2992.56,3712.44 3170,3535 3170,2785 3010,2625 2375,2625 2250,2500 2250,2215 2215,2180 1925,2180 1915,2190
NetD7_1 on Bottom Layer "Bottom Layer-No Net 1" (solid, pour order 97): 965,2860 1035,2860 1035,2664.88 1060,2639.88 1640.12,2639.88 1845,2435 1845,1885.43 1570,1610.43 1080.43,1610.43 1030,1560 1030,1400 960,1400 965,1405 965,1570 950,1585 950,1655 1055,1760 1236,1760 1500,2025 1500,2185 1395,2290 740,2290 740,2595 800,2655 940,2655 960,2675 960,2855
NetC18_1 on Bottom Layer "Bottom Layer-No Net" (solid, pour order 92): 735,2240 740,2235 1385,2235 1450,2170 1450,2040 1225,1815 1015,1815 840,1615 840,1600 495,1255 495,1115 750,860 750,25 -23.35,25 -33.35,35 -33.35,1701.65 15,1750 550,1750 690,1890 690,1895 735,1940
GND-S on Bottom Layer "Bottom Layer-No Net 15" (solid, pour order 113): 3480.24,490.2 3480.24,726.42 3460.55,746.1 3303.07,746.1 3303.07,751.02 3283.39,765.79 3283.39,803.2 3501.87,803.2 3519.61,785.47 3519.61,490.2
GND-S on Bottom Layer "Bottom Layer-No Net 18" (solid, pour order 118): 2057.91,4994.69 2097.28,5034.06 2156.34,5034.06 2195.71,5073.43 2274.45,5073.43 2294.13,5053.74 2294.13,5003.54 2294.13,4856.89 2274.45,4837.2 2077.6,4837.2 2057.91,4856.89 2057.91,4994.69
+5V on Bottom Layer "Bottom Layer-No Net 19" (solid, pour order 103): 7471.3,4388.78 7471.3,4167.91 7451.61,4148.23 7215.39,4148.23 7195.71,4167.91 7195.71,4502.56 7174.53,4523.74 7136.99,4523.74 7136.99,4640.02 7136.65,4640.35 7156.34,4660.04 7294.13,4660.04 7303.98,4650.2 7303.98,4413.98 7313.82,4404.13 7455.94,4404.13
NetL3_1 on Bottom Layer "Bottom Layer-No Net 5" (solid, pour order 101): 5010.67,2585 5010.67,1830 4560,1830 4560,2585
GND-S on Bottom Layer "Bottom Layer-No Net 9" (solid, pour order 84): 4984.83,1092.05 5796.62,1092.05 5795,1090.43 5795,1020 5795,1000 5760,965 5760,590 5755,585 5150,585 4984.83,750.17 4984.83,1092.05
GND-S on Bottom Layer "Bottom Layer-No Net 10" (solid, pour order 88): 7100,1095 6420,1095 6420,835 6435,820 6435,815 6435,620 6465,590 7100,590
GND-S on Bottom Layer "Bottom Layer-No Net 10" (solid, pour order 86): 6620,3247.5 7300,3247.5 7300,3507.5 7285,3522.5 7285,3527.5 7285,3722.5 7255,3752.5 6620,3752.5
GND-S on Bottom Layer "Top Layer-No Net 4" (solid, pour order 117): 4985,1060 7055,1060 7055,50 9000,50 9002.95,1679.13 9002.95,2315 9000,3385 10245,3380 10242.01,4225.08 9203.58,4226.97 8215,4225 8215,4095 8540.65,3695 8540,3385 5890,3385 5890,3760 4355,3765 4355,3220 4705,3220 4975,2950
NetC58_2 on Bottom Layer "Bottom Layer-No Net 11" (solid, pour order 87): 8715,2740 8835,2740 9080,2985 9775,2985 9800,2960 9800,2265 9710,2175 8715,2175
NetC58_1 on Bottom Layer "Bottom Layer-No Net 12" (solid, pour order 90): 9835,2980 9835,2175 10075,2175 10120,2220 10120,2945 10085,2980 9880,2980
NetC58_1 on Bottom Layer "Bottom Layer-No Net 13" (solid, pour order 93): 9025,1600 9775,1600 9775,1225 9775,1200 9025,1200
EARTH on Bottom Layer "Bottom Layer-No Net 16" (solid, pour order 121): 9045,2130 10201.63,2130 10242.01,2089.61 10242.01,97.01 10205,60 9100,60 9055,105 9055,2130
NetL3_1 on Top Layer "Top Layer-No Net 3" (solid, pour order 112): 4570,2565 5582.3,2565.89 5880,2565 6040,2410 6040,1860 5920,1760 5675,1760 5575,1860 4570,1860 4569.72,2000.04
NetD13_1 on Top Layer "Top Layer-No Net 2" (solid, pour order 111): 4575,1825 5325.63,1822.87 5545,1825 5640,1730 5945,1730 6050,1825 6460,1825 6705,1570 6705,1175 4870,1180 4695.71,1350.43 4577.6,1468.54
NetD13_3 on Top Layer "Top Layer-No Net 1" (solid, pour order 110): 4577.6,3141.77 4750,3315 6725,3315 6725,2945 6390.98,2610 4575,2610 4577.6,2748.07
GND-S on Top Layer "Top Layer-No Net 8" (solid, pour order 109): 5679.96,3133.35 5679.96,3822.32 5680,3860 5680,3895 5725,3940 6255,3940 6255,3830 6215.39,3829.21 6191.77,3806.57 6191.77,3741.61 6176.02,3726.42 6076.18,3726.42 6053.98,3704.21 6053.98,3629.41 6077.76,3605.63 6703.74,3605.63 6802.01,3507.36 6802.01,3172.72 6800,3230 5680,3230
NetC31_2 on Top Layer "Top Layer-No Net 11" (solid, pour order 104): 1840,1530 1905,1530 1910,1525 1910,1315 1905,1320 1835,1320 1835,1525
NetC31_2 on Top Layer "Top Layer-No Net 10" (solid, pour order 102): 835,1530 920,1530 930,1520 930,1380 945,1365 955,1355 2020,1355 2075,1410 2075,1520 2120,1565 2345,1565 2525,1745 2845,1745 2920,1670 2920,1365 2785,1230 2720,1230 2600,1110 2600,1020 2415,835 2055,835 1985,905 1985,965 1880,1070 1840,1110 1449.37,1110 1422.72,1083.35 1189.48,1083.35 1150.31,1044.18 875.82,1044.18 820,1100 820,1515
NetC30_2 on Top Layer "Top Layer-No Net 6" (solid, pour order 98): 1050,2895 1052.59,2687.41 1050,2690 1613.13,2690 1649.28,2726.15 1650,2915 1885,2915 1998.35,3035 1998.35,3038.55 2008.55,3038.55 2150,3180 2900,3180 3165,3445 3165,4115 3130,4150 2785,4150 2485,3850 2485,3815 2120,3450 2045,3450 1880.43,3285.43 1409.57,3285.43 1585,3285
NetC30_2 on Top Layer "Top Layer-No Net 9" (solid, pour order 100): 1900,2725 1900,2938.25 1925,2963.25 1794.9,2963.25 1794.9,2920.1 1835,2880 1835,2725
GND-P on Top Layer "Bottom Layer-No Net 2" (solid, pour order 99): 1610,1645 1900,1645 1805,1550 1805,1405 1730,1405 1730,1450 1610,1450
GND-P on Top Layer "Top Layer-No Net" (solid, pour order 91): -55,30 1220,30 1225,35 1225,740 1195,770 1000,770 770,1000 610,1000 495,1115 495,1255 670,1430 735,1500 840,1615 2308.23,1615 2483.23,1790 2483.23,2761.77 2350,2895 1955,2895 1945,2885 1945,2880 1935,2870 1935,2695 1890,2650 1480,2650 1440,2610 1440,2060 1275,1895 690,1895 675,1870 580,1780 470,1750 15,1750 -55,1665
GND-S on Top Layer "Top Layer-No Net 7" (solid, pour order 114): 5480,1245 5479.17,1062.2 5561.85,979.53 5561.85,782.68 5620.91,723.62 5705,640 6053.98,640.94 6124.84,640.94 6465,640 6546.1,723.62 6589.41,766.93 6590,1245
VOUT on Top Layer "Top Layer-No Net 5" (solid, pour order 89): 7110,3190 7650,3190 7650,1360 7650,1300 7850,1100 8800,1100 8860,1040 8860,920 8860,240 8860,120 8800,60 7060,60 7055,65 7055,1060 6750,1365 6750,1570 6450,1870 6440,1870 6110,1870 6110,2500 6440,2500 7130,3190
NetC57_1 on Top Layer "Top Layer-No Net 12" (solid, pour order 95): 7690,3190 8655,3190 8650,3185 8650,1180 7825.25,1180 7695.24,1310.01
NetC58_2 on Top Layer "Bottom Layer-No Net 13" (solid, pour order 81): 9025,2715 9070,2760 9660,2760 9725,2695 9725,2480 9660,2410 9075,2410 9025,2460
NetC58_1 on Top Layer "Top Layer-No Net 13" (solid, pour order 83): 8695,3170 9010,3355 10215,3355 10250,3320 10250,1165 10215,1130 8880,1130 8845,1165 8720,1165 8720,1166.89 8695,1191.89
GND-S on Top Layer "Top Layer-gndx" (solid, pour order 115): 500,5850 500,4275 2525,4275 2765,4545 3380,4550 4100,3940 4100,3910 5483.11,3912.01 5679.96,4108.86 8000,4110 8205,4110 8530,3715 8695,3405 9025,3405 10250,3403.15 10250,5825 10225,5825 4656.34,5841.14 4636.65,5839 4242.95,5839 4105.16,5841.14
GND-S on Top Layer "Bottom Layer-No Net 14" (solid, pour order 108): 3298.07,428.27 3416.18,428.27 3435.87,449.37 3435.87,702.46 3435,951.72 3680,1190 3680,3000 3970,3230 3970,4070 5110,4070 4620,3580 4620,3430 4360,3170 4360,530 4203.58,365 3317.76,365 3298.07,386.09

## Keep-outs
Keep-Out Layer:
  lines w10: -78.74,5 -78.74,3450 ; -78.74,5900 10287.4,5900 10287.4,5
  text ".Layer_Name" at 577,-858.49 h60

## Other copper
Top Layer:
  pour cut-out: 9925,5675 10065,5675 10140,5615 10155,5595 10165,5580 10165,5440 10070,5345 9930,5345 9845,5430 9845,5590 9850,5600
  pour cut-out: 126.12,558.7 266.12,558.7 341.12,498.7 356.12,478.7 366.12,463.7 366.12,323.7 271.12,228.7 131.12,228.7 46.12,313.7 46.12,473.7 51.12,483.7
  pour cut-out: 4675,5670 4815,5670 4890,5610 4905,5590 4915,5575 4915,5435 4820,5340 4680,5340 4595,5425 4595,5585 4600,5595
  text ".Layer_Name" at 577,-858.49 h60
Bottom Layer:
  pour cut-out: 9925,5675 10065,5675 10140,5615 10155,5595 10165,5580 10165,5440 10070,5345 9930,5345 9845,5430 9845,5590 9850,5600
  pour cut-out: 132.5,562.5 272.5,562.5 347.5,502.5 362.5,482.5 372.5,467.5 372.5,327.5 277.5,232.5 137.5,232.5 52.5,317.5 52.5,477.5 57.5,487.5
  pour cut-out: 4675,5670 4815,5670 4890,5610 4905,5590 4915,5575 4915,5435 4820,5340 4680,5340 4595,5425 4595,5585 4600,5595
  text "UL94V-0" at 2529.5,86.5 h60
  text ".Layer_Name" at 577,-858.49 h60

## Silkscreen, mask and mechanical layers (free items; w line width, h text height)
Top Overlay:
  circle w10: c7495,350 r262.49
  circle w10: c8050,350 r262.49
  circle w10: c8600,350 r262.49
  circle w10: c8600,900 r262.49
  circle w10: c8050,905 r262.49
  circle w10: c7500,900 r262.49
  lines w11.81: 450,2705 2418.5,2705 2418.5,3886.1 450,3886.1 450,2705 ; 456.5,360 456.5,1541.1 2425,1541.1 2425,360 456.5,360 ; 5106.5,3150 7075,3150 7075,4331.1 5106.5,4331.1 5106.5,3150 ; 5126.5,105 7095,105 7095,1286.1 5126.5,1286.1 5126.5,105
  lines w19.68: 1250,1722.6 1250,2510 2470.47,2510 2470.47,1722.6 1250,1722.6
  text "This document can handle board shapes up to 7.9in x 10in, although" at 6070,11425 h60
  text "our panel vendors top out at 7in x 10in." at 6070,11300.94 h60
  text "To re-size the board shape, do the following:" at 6125,11176.88 h60
  text "Select lines on M1 Board Outline and delete (easy in single layer mode...shift+s)" at 6185,11052.82 h60
  text "Draw a rectangle using lines (example will be for a 4\" x 6\" board" at 6185,10928.76 h60
  text "Enter Place Line mode (keyboard pl)" at 6395,10804.71 h60
  text "keyboard jo to jump to origin, hit enter" at 6395,10680.65 h60
  text "keyboard jl to jump to location, set x to 6000, hit enter twice" at 6395,10556.59 h60
  text "keyboard jl to jump to location, set x to 6000 and y to 4000, hit enter twice" at 6570,10460 h60
  text "keyboard jl to jump to location, set x to 0 and y to 4000, hit enter twice" at 6395,10308.47 h60
  text "keyboard jo to jump to origin, hit enter" at 6395,10184.41 h60
  text "Hit ESC twice to exit place line mode" at 6395,10060.35 h60
  text "Select lines on M1 Board Outline" at 6185,9916.3 h60
  text "Menu Design|Board Shape|Define from Selected Objects (keyboard dsd)" at 6185,9812.24 h60
  text "To define a Keep-Out that mirrors the board outline:" at 6070,9688.18 h60
  text "Menu Design|Board Shape|Create Primitives From Board Shape (keyboard dsp)" at 6185,9564.12 h60
  text "Set the Keep-Out Layer as the layer, set width as preferred" at 6395,9440.06 h60
  text "Ensure Route Tool Outline is selected, hit enter" at 6395,9316 h60
  text "If you re-size the board, don't forget to move the drill table strings on the" at 6070,8993 h60
  text "Drill Drawing Layer...they should be just to the right of your board shape" at 6263,8887 h60
  text "2KW Battery Charger" at 4725,5025 h40
  text "Full Bridge Stage" at 4760,4935 h40
  text "PMP8740 Rev_C" at 4835,4845 h40
  text ".Layer_Name" at 577,-858.49 h60
Bottom Overlay:
  rectangle: 3435.87,51.22 3735.87,151.22
  text ".PCB_Rev" at 1473,285 h60
  text ".PRJ_Number" at 4401.87,61.22 h60
  text "-" at 3800.87,50.72 h60
  text ".Layer_Name" at 577,-858.49 h60
Top Paste:
  text ".Layer_Name" at 577,-858.49 h60
Bottom Paste:
  text ".Layer_Name" at 577,-858.49 h60
Top Solder:
  lines w10: 4710,1595 4775,1585 4755,1650 4710,1595
  text ".Layer_Name" at 577,-858.49 h60
  text ".Layer_Name" at 577,-858.49 h60
Bottom Solder:
  text ".Layer_Name" at 577,-858.49 h60
Drill Guide:
  text ".Layer_Name" at 577,-858.49 h60
M1 Board Outline:
  lines w10: -78.74,5 10287.4,5 10287.4,5900 -78.74,5900 -78.74,5
  text ".Layer_Name" at 577,-858.49 h60
M2 Board Dimensions:
  rectangle: 124.5,-410.5 499.5,-285.5
  lines w7: -0.5,-285.5 999.5,-285.5 ; 124.5,-410.5 124.5,-160.5 ; 249.5,-410.5 249.5,-160.5 ; 499.5,-410.5 499.5,-160.5 ; 749.5,-410.5 749.5,-160.5 ; -0.5,-410.5 -0.5,-160.5 999.5,-160.5 999.5,-410.5 -0.5,-410.5
  lines w10: -0.5,-475.5 -0.5,-455.5 ; 59.5,-485.5 -0.5,-465.5 ; 59.5,-445.5 -0.5,-465.5 ; 223.58,-465.5 -0.5,-465.5 ; 775.42,-465.5 999.5,-465.5 ; 939.5,-485.5 999.5,-465.5 ; 939.5,-445.5 999.5,-465.5 ; 999.5,-475.5 999.5,-455.5
  text "1000 (mil)" at 233.58,-501.49 h60
  text ".Layer_Name" at 577,-858.49 h60
M3 3D STEP Top:
  text ".Layer_Name" at 577,-858.49 h60
M4 3D STEP Bottom:
  text ".Layer_Name" at 577,-858.49 h60
M5 Assembly Top:
  lines w10: -292,-930.17 6308,-930.17 ; -292,-726.83 6310,-726.83 ; -292,-523.5 -292,-1133.5 3713,-1133.5 6310,-1133.5 6310,-523.5 -291.5,-523.5 -291.5,-1133.5 1284,-1133.5 ; 380,360 2475,360 ; 770,2640 770,2545.21 1220,2545.21 1220,2640.21 ; 777.64,1613.27 777.64,1708.27 1227.64,1708.27 1227.64,1613.47 ; 1645,1613.27 1645,1708.27 2095,1708.27 2095,1613.47 ; 1645,2635 1645,2540.21 2095,2540.21 2095,2635.21 ; 2173,-1133.5 2173,-523.5 ; 3440,-726.83 3440,-523.5 ; 4280,-726.83 4280,-523.5 ; 4902,-1140 4902,-937.17 ; 5420,3087.5 5420,3035 5895,3035 5895,3087.27 ; 5448.76,1336.57 5448.76,1396.57 5923.76,1396.57 ; 5913.03,1475 5913.03,2975 ; 5914.02,2975 6665,2975 6665,1475 ; 5926.05,1340.08 5926.05,1400.08 ; 6271.77,1342.46 6271.77,1395 6746.77,1395 6746.77,1350 ; 6295,3080 6295,3035 6770,3035 6770,3086.86 ; 7066.93,-1534 7637.8,-1534 ; 7218.9,3342.6 7218.9,4130 ; 7220,4140 8400,4140 ; 7223.9,3347.6 8405,3347.6 ; 8400,3347.6 8400,4135
  text "COMPONENTS MARKED 'DNP' SHOULD NOT BE POPULATED." at 1153.5,-318.5 h60
  text "ASSEMBLY VARIANT:" at 1153,-434 h60
  text ".VariantName" at 2189,-434 h60
  text "PCB VIEWED FROM TOP SIDE" at -228.5,-655.67 h60
  text "BOARD #:" at 2248,-655.67 h60
  text ".PRJ_Number" at 2793.5,-655.67 h60
  text "REV:" at 3638,-655.67 h60
  text ".PCB_Rev" at 3929.5,-655.67 h60
  text "SVN REV:" at 4476,-655.67 h60
  text ".VersionControl_RevNumber" at 4982,-655.67 h60
  text "IGNORE ->" at -228.5,-858.49 h60
  text "PLOT NAME =" at -228.5,-1064.34 h60
  text ".plot_File_Name" at 577,-1064.34 h60
  text "GENERATED    :" at 2250,-1064.34 h60
  text ".Print_Date" at 3119.5,-1064.34 h60
  text ".Print_Time" at 3848.5,-1064.34 h60
  text "TEXAS INSTRUMENTS" at 5113,-1064.34 h60
M6 Assembly Bottom:
  lines w10: -292.5,-727.33 6309.5,-727.33 ; -290.5,-930.67 6309.5,-930.67 ; 1115.5,-1140.5 1115.5,-937.67 ; 1737.5,-727.33 1737.5,-524 ; 2577.5,-727.33 2577.5,-524 ; 3844.5,-1134 3844.5,-524 ; 4733.5,-1134 6309,-1134 6309,-524 -292.5,-524 -292.5,-1134 2304.5,-1134 6309.5,-1134 6309.5,-524
  text "COMPONENTS MARKED 'DNP' SHOULD NOT BE POPULATED." at 6102,-318 h60
  text ".VariantName" at 5058,-434 h60
  text "ASSEMBLY VARIANT:" at 6097,-434 h60
  text ".VersionControl_RevNumber" at 1035.5,-656.17 h60
  text "SVN REV:" at 1541.5,-656.17 h60
  text ".PCB_Rev" at 2088,-656.17 h60
  text "REV:" at 2379.5,-656.17 h60
  text ".PRJ_Number" at 3224,-656.17 h60
  text "BOARD #:" at 3769.5,-656.17 h60
  text "PCB VIEWED FROM BOTTOM SIDE" at 6246,-656.17 h60
  text "IGNORE ->" at 2547.85,-858.49 h60
  text "TEXAS INSTRUMENTS" at 904.5,-1064.84 h60
  text ".Print_Time" at 2169,-1064.84 h60
  text ".Print_Date" at 2898,-1064.84 h60
  text "GENERATED    :" at 3767.5,-1064.84 h60
  text ".plot_File_Name" at 5440.5,-1064.84 h60
  text "PLOT NAME =" at 6246,-1064.84 h60
M9 Title Sheet:
  lines w10: -491.5,1041.5 -291.5,1041.5 ; -491.5,3416.5 -291.5,3416.5 ; -491.5,5791.5 -291.5,5791.5 ; 2008.5,-1333.5 2008.5,-1133.5 ; 2008.5,7966.5 2008.5,8166.5 ; 4508.5,-1333.5 4508.5,-1133.5 ; 4508.5,7966.5 4508.5,8166.5 ; 6321,-1133.5 6321,-523.5 11303.5,-523.5 ; 7008.5,-1333.5 7008.5,-1133.5 ; 7008.5,7966.5 7008.5,8166.5 ; 9508.5,-1333.5 9508.5,-1133.5 ; 9508.5,7966.5 9508.5,8166.5 ; 11303.5,-1133.5 11303.5,-523.5 ; 11303.5,-823.5 14303.5,-823.5 ; 11303.5,-223.5 14303.5,-223.5 ; 11303.5,76.5 11303.5,-523.5 ; 12008.5,-1333.5 12008.5,-1133.5 ; 12008.5,7966.5 12008.5,8166.5 ; 12808.5,-1123.5 12808.5,-523.5 ; 14303.5,-523.5 11303.5,-523.5 ; 14308.5,66.5 14308.5,-1133.5 ; 14308.5,-1133.5 -291.5,-1133.5 -291.5,7966.5 14308.5,7966.5 14308.5,-1133.5 ; -491.5,-1333.5 14508.5,-1333.5 14508.5,8166.5 -491.5,8166.5 -491.5,-1333.5
  text "1" at 739.84,8036.5 h70
  text "2" at 3235.5,8036.5 h70
  text "3" at 5724.84,8036.5 h70
  text "4" at 8231.51,8036.5 h70
  text "5" at 10730.5,8036.5 h70
  text "6" at 13235.5,8036.5 h70
  text "A" at -416.5,6893.5 h70
  text "A" at 14383.5,6893.5 h70
  text "B" at -416.5,4513.5 h70
  text "C" at -416.5,2138.5 h70
  text "DESIGNED FOR:" at 11343.5,-23.5 h45
  text ".PRJ_Customer" at 11393.5,-163.5 h70
  text "D" at -416.5,-231.5 h70
  text "D" at 14383.5,-231.5 h70
  text "FILE NAME:" at 11343.5,-323.5 h45
  text ".PCB_File_Name_No_Path" at 11393.5,-443.5 h70
  text "Texas Instruments (TI) and/or its licensors do not warrant the accuracy or completeness of this specification" at 6374,-605.34 h45
  text "ENGINEER:" at 11343.5,-613.5 h45
  text "LAYOUT BY:" at 12848.5,-613.5 h45
  text "or any information contained therein. TI and/or its licensors do not warrant that this design will meet" at 6329.01,-718 h45
  text ".PRJ_Engineer" at 11393.5,-768.49 h70
  text ".PCB_Layout" at 12899,-768.49 h70
  text "the specifications, will be suitable for your application or fit for any particular purpose, or will operate in" at 6329.01,-830.67 h45
  text ".Layer_Name" at 577,-858.49 h60
  text "ALTIUM DESIGNER VERSION:" at 12848.5,-923.5 h45
  text "an implementation. TI and/or its licensors do not warrant that the design is production worthy. You should" at 6329.01,-943.33 h45
  text "completely validate and test your design implementation to confirm the system functionality for your application." at 6374,-1056 h45
  text ".print_Scale" at 11393.5,-1056.83 h70
  text ".Application_BuildNumber" at 12899,-1056.83 h70
  text "1" at 739.84,-1263.5 h70
  text "2" at 3235.5,-1263.5 h70
  text "3" at 5724.84,-1263.5 h70
  text "4" at 8231.51,-1263.5 h70
  text "5" at 10730.5,-1263.5 h70
  text "6" at 13235.5,-1263.5 h70
M10 Fab Notes:
  lines w8: 11713.46,6493 12195.46,6493 ; 12450.46,6493 12932.46,6493 ; 12750,6287 12955.39,6287
  lines w20: 11303,876 11303,6909 14294,6909 14294,876 ; 11303,6771 14294,6771
  text "DESIGN INFORMATION" at 12381.02,6810 h60
  text "(REFER ALSO ARRAY/PANEL PROFILING INFORMATION)" at 12019.46,6648.29 h60
  text "BOARD SIZE" at 11333.46,6644 h60
  text "3450MIL" at 11795.78,6516.18 h60
  text "X" at 12301.46,6516.18 h60
  text "4950MIL" at 12532.78,6516.18 h60
  text "Number of Layers :" at 11736.46,6319 h60
  text "2" at 12831.27,6309 h60
  text ".Layer_Name" at 577,-858.49 h60
M11 Gerber Information:
  lines w10: -292,-930.17 6308,-930.17 ; -292,-726.83 6310,-726.83 ; -292,-523.5 -292,-1133.5 3713,-1133.5 6310,-1133.5 6310,-523.5 -291.5,-523.5 -291.5,-1133.5 1284,-1133.5 ; 2173,-1133.5 2173,-523.5 ; 3440,-726.83 3440,-523.5 ; 4280,-726.83 4280,-523.5 ; 4902,-1140 4902,-937.17
  text "ALL ARTWORK VIEWED FROM TOP SIDE" at -228.5,-655.67 h60
  text "BOARD #:" at 2248,-655.67 h60
  text ".PRJ_Number" at 2793.5,-655.67 h60
  text "REV:" at 3638,-655.67 h60
  text ".PCB_Rev" at 3929.5,-655.67 h60
  text "SVN REV:" at 4476,-655.67 h60
  text ".VersionControl_RevNumber" at 4982,-655.67 h60
  text "LAYER NAME =" at -228.5,-858.49 h60
  text "PLOT NAME =" at -228.5,-1064.34 h60
  text ".plot_File_Name" at 577,-1064.34 h60
  text "GENERATED    :" at 2250,-1064.34 h60
  text ".Print_Date" at 3119.5,-1064.34 h60
  text ".Print_Time" at 3848.5,-1064.34 h60
  text "TEXAS INSTRUMENTS" at 5113,-1064.34 h60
